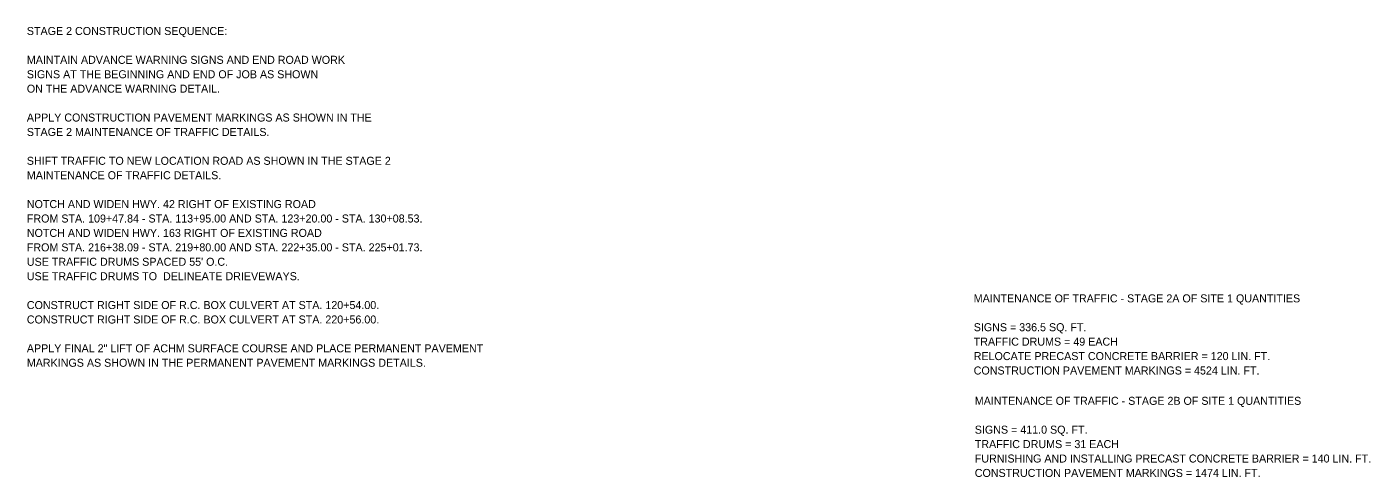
# Model space of a CAD drawing. Extents: x 1678017 to 1687792, y 404433 to 413488.
# Drawn here: x 1682425 to 1683432, y 411826 to 412163 of the extents above; entities that cross this region are included whole.
import ezdxf

# ---------------------------------------------------------------- set-up
doc = ezdxf.new("R2010")
doc.units = 0
doc.layers.add('S_MSC_PT_SYM', color=7, linetype='Continuous')

msp = doc.modelspace()

# ---------------------------------------------------------------- texts
at = {"layer": 'S_MSC_PT_SYM'}
for s, p in [('STAGE 2 CONSTRUCTION SEQUENCE:', (1682425, 412157.2)), ('MAINTAIN ADVANCE WARNING SIGNS AND END ROAD WORK', (1682425, 412135.6)), ('SIGNS AT THE BEGINNING AND END OF JOB AS SHOWN', (1682425, 412124.8)), ('ON THE ADVANCE WARNING DETAIL.', (1682425, 412114)), ('APPLY CONSTRUCTION PAVEMENT MARKINGS AS SHOWN IN THE', (1682425, 412092.4)), ('STAGE 2 MAINTENANCE OF TRAFFIC DETAILS.', (1682425, 412081.6)), ('SHIFT TRAFFIC TO NEW LOCATION ROAD AS SHOWN IN THE STAGE 2', (1682425, 412060)), ('MAINTENANCE OF TRAFFIC DETAILS.', (1682425, 412049.2)), ('NOTCH AND WIDEN HWY. 42 RIGHT OF EXISTING ROAD ', (1682425, 412027.6)), ('FROM STA. 109+47.84 - STA. 113+95.00 AND STA. 123+20.00 - STA. 130+08.53.', (1682425, 412016.8)), ('NOTCH AND WIDEN HWY. 163 RIGHT OF EXISTING ROAD', (1682425, 412006)), ('FROM STA. 216+38.09 - STA. 219+80.00 AND STA. 222+35.00 - STA. 225+01.73.', (1682425, 411995.2)), ("USE TRAFFIC DRUMS SPACED 55' O.C.", (1682425, 411984.4)), ('USE TRAFFIC DRUMS TO  DELINEATE DRIEVEWAYS.', (1682425, 411973.6)), ('MAINTENANCE OF TRAFFIC - STAGE 2A OF SITE 1 QUANTITIES', (1683134.8, 411957)), ('CONSTRUCT RIGHT SIDE OF R.C. BOX CULVERT AT STA. 120+54.00.', (1682425, 411952)), ('CONSTRUCT RIGHT SIDE OF R.C. BOX CULVERT AT STA. 220+56.00.', (1682425, 411941.2)), ('SIGNS = 336.5 SQ. FT.', (1683134.8, 411935.4)), ('TRAFFIC DRUMS = 49 EACH', (1683134.8, 411924.6)), ('APPLY FINAL 2" LIFT OF ACHM SURFACE COURSE AND PLACE PERMANENT PAVEMENT', (1682425, 411919.6)), ('MARKINGS AS SHOWN IN THE PERMANENT PAVEMENT MARKINGS DETAILS.', (1682425, 411908.8)), ('RELOCATE PRECAST CONCRETE BARRIER = 120 LIN. FT.', (1683134.8, 411913.8)), ('CONSTRUCTION PAVEMENT MARKINGS = 4524 LIN. FT.', (1683134.8, 411903)), ('MAINTENANCE OF TRAFFIC - STAGE 2B OF SITE 1 QUANTITIES', (1683135.6, 411880.3)), ('SIGNS = 411.0 SQ. FT.', (1683135.6, 411858.7)), ('TRAFFIC DRUMS = 31 EACH', (1683135.6, 411847.9)), ('FURNISHING AND INSTALLING PRECAST CONCRETE BARRIER = 140 LIN. FT.', (1683135.6, 411837.1)), ('CONSTRUCTION PAVEMENT MARKINGS = 1474 LIN. FT.', (1683135.6, 411826.3))]:
    msp.add_text(s, height=6, dxfattribs=at).set_placement(p)

doc.saveas('drawing.dxf')
